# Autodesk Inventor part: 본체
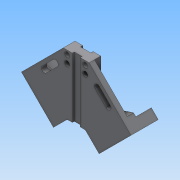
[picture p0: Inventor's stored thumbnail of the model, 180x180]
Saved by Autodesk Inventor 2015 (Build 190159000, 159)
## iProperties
Created: 2019-04
Part Number: 본체
Material: 일반
Document SubType Name: Modeling
Designer: SCD-A01
Density: 1 g/cm^3
Appearance: 기본값
Author: SCD-A01
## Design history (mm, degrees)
sketch "스케치1"
  geometry: L1 (84.853, 0)-(0, 84.853); L2 (0, 84.853)-(-84.853, 0); L3 (-84.853, 0)-(0, -84.853); L4 (0, -84.853)-(84.853, 0); L5 (84.853, 0)-(-84.853, 0); L6 (0, -84.853)-(0, 84.853); L7 (100, 0)-(-100, 0); 4 further points
  constraints: 14 end point, 3 midpoint, 2 coincident, 2 perpendicular, 1 horizontal, 1 point on line
  dimensions: "d2" = 120 distance of L1.start L1.end; "d3" = 120 distance of L1.end L2.end; "d4" = 120 distance of L2.end L3.end; "d5" = 200 distance of L7.start L7.end
extrude "돌출1" new body sketch "스케치1" distance "d6" = 42; taper "d7" = 0 deg
sketch "스케치2"
  geometry: L1 (-84.853, 0)-(0, -84.853) reference; L2 (-20, -64.853)-(20, -64.853); L3 (-20, -64.853)-(0, -84.853); L4 (20, -64.853)-(0, -84.853); 1 further point
  constraints: 6 end point, 1 horizontal, 1 point on line
  dimensions: "d8" = 40 distance of L2.start L2.end; "d9" = 20 distance from line of L1.end L2
extrude "돌출2" cut sketch "스케치2" distance "d10" = 42; taper "d11" = 0 deg
sketch "스케치3"
  geometry: L1 (-20, -64.853)-(20, -64.853) reference; L2 (0, -64.853)-(0, 28.147); L3 (-84.853, 0)-(0, 84.853); L4 (84.853, 0)-(0, 84.853) reference; L5 (-14.005, 28.147)-(14.005, 28.147); L6 (-14.005, 28.147)-(-35.355, 49.497); L7 (14.005, 28.147)-(35.355, 49.497); L8 (-35.355, 49.497)-(0, 84.853); L9 (0, 84.853)-(35.355, 49.497); 1 further point
  constraints: 14 end point, 2 midpoint, 1 collinear, 1 horizontal, 1 parallel, 1 perpendicular, 1 vertical
  dimensions: "d12" = 93 distance of L2.end L2.start; "d22" = 50 distance between parallel lines of L3 L7; "d23" = 50 distance between parallel lines of L4 L6
extrude "돌출3" cut sketch "스케치3" distance "d24" = 42; taper "d25" = 0 deg
sketch "스케치4"
  geometry: L1 (-35.355, 49.497)-(-84.853, 0) reference; L2 (84.853, 0)-(35.355, 49.497) reference; L3 (-24.749, 38.891)-(-74.246, -10.607); L4 (74.246, -10.607)-(24.749, 38.891); L5 (-74.246, -10.607)-(0, -84.853); L6 (0, -84.853)-(74.246, -10.607); L7 (-24.749, 38.891)-(24.749, 38.891); 1 further point
  constraints: 10 end point, 2 parallel, 1 horizontal
  dimensions: "d26" = 15 distance between parallel lines of L1 L3; "d27" = 15 distance between parallel lines of L2 L4; "d28" = 49.49747 distance of L3.start L4.end; "d30" = 74.24621 horizontal distance of L3.end L5.end; "d31" = 105 distance of L5.end L4.start; "d32" = 90 deg angle of L6 L5; "d33" = 148.49242 distance of L4.start L3.end
extrude "돌출4" cut sketch "스케치4" distance "d34" = 24; taper "d35" = 0 deg
sketch "스케치5"
  geometry: L1 (40, 18)-(0, 18) reference; L2 (12, 18)-(12, 14.5); L3 (12, 14.5)-(28, 14.5); L4 (28, 14.5)-(28, 18); L5 (28, 18)-(12, 18); 2 further points
  constraints: 8 end point, 3 perpendicular, 2 midpoint, 1 vertical
  dimensions: "d39" = 16 distance between parallel lines of L4 L2; "d40" = 3.5 distance of L2.start L2.end
extrude "돌출5" cut sketch "스케치5" stored distance "d41" = 24; taper "d42" = 0 deg
sketch "스케치6"
  geometry: L1 (40, 0)-(0, 0) reference; L2 (14, 0)-(14, 3); L3 (14, 3)-(26, 3); L4 (26, 3)-(26, 0); L5 (26, 0)-(14, 0); 2 further points
  constraints: 8 end point, 2 midpoint, 2 perpendicular, 2 vertical
  dimensions: "d43" = 3 distance of L3.end L4.end; "d44" = 12 distance of L2.end L3.end
extrude "돌출6" cut sketch "스케치6" stored distance "d45" = 24; taper "d46" = 0 deg
sketch "스케치7"
  geometry: L1 (-20, -64.853)-(-74.246, -10.607) reference; L2 (-12.649, -58.062)-(-66.895, -3.816); L3 (-35.355, 49.497)-(-84.853, 0) reference; L4 (-21.213, 35.355)-(-70.711, -14.142); L5 (-12.461, 29.965)-(-61.959, -19.532); L6 (-5.438, -51.131)-(-59.684, 3.115); L7 (-70.711, -14.142)-(-49.497, -7.071); L8 (-26.541, 1.743)-(-76.039, -47.754); L9 (-9.571, -15.228)-(-59.068, -64.725); L10 (-20, -64.853)-(-20, -36.569); L11 (-20, -36.569)-(-49.497, -7.071); L12 (-70.711, -14.142)-(-20, -64.853); 1 further point
  constraints: 20 end point, 6 parallel, 3 point on line, 1 perpendicular, 1 vertical
  dimensions: "d47" = 10 distance between parallel lines of L1 L2; "d48" = 20 distance between parallel lines of L3 L4; "d49" = 30 distance between parallel lines of L3 L5; "d50" = 20 distance between parallel lines of L1 L6; "d51" = 40 distance between parallel lines of L3 L8; "d52" = 24 distance between parallel lines of L8 L9; "d54" = 21.2132 horizontal distance of L4.end L7.end
extrude "돌출7" cut sketch "스케치7" distance "d55" = 10; taper "d56" = 0 deg
sketch "스케치8"
  geometry: L1 (-7.071, 21.213)-(-56.569, -28.284); L2 (9.899, 4.243)-(-39.598, -45.255); L3 (-84.853, 0)-(-20, -64.853) reference; L4 (-77.782, 7.071)-(-12.929, -57.782); L5 (-35.355, 49.497)-(-84.853, 0) reference; L6 (-49.497, -21.213)-(-32.527, -38.184); L7 (-52.679, -24.395)-(-35.709, -41.366); L8 (-29.345, -35.002)-(-46.315, -18.031); A1 r 4.5 centre (-49.497, -21.213) between (-46.315, -18.031) and (-52.679, -24.395); A2 r 4.5 centre (-32.527, -38.184) between (-35.709, -41.366) and (-29.345, -35.002); 2 further points
  constraints: 14 end point, 4 point on circle, 4 point on line, 4 tangent, 3 parallel, 2 centre point, 1 midpoint
  dimensions: "d58" = 24 distance between parallel lines of L1 L2; "d59" = 10 distance between parallel lines of L3 L4; "d60" = 40 distance between parallel lines of L1 L5; "d61" = 9 diameter of A2
extrude "돌출8" cut sketch "스케치8" distance "d62" = 10; taper "d63" = 0 deg
sketch "스케치9"
  geometry: L1 (20, -64.853)-(8, -64.853) reference; L2 (0, 0)-(0, -70); L3 (20, -58.853)-(8, -58.853); L4 (14, 0)-(14, -70); C1 r 2.25 at (14, -58.853)
  constraints: 6 end point, 2 parallel, 1 centre point, 1 midpoint, 1 point on line, 1 vertical
  dimensions: "d64" = 70 distance of L2.start L2.end; "d65" = 6 distance between parallel lines of L1 L3; "d66" = 14 distance between parallel lines of L2 L4; "d67" = 4.5 diameter of C1
extrude "돌출9" cut sketch "스케치9" distance "d68" = 8; taper "d69" = 0 deg
sketch "스케치10"
  geometry: C1 r 2.25 at (14, 58.853) reference; C2 r 4 at (14, 58.853); 1 further point
  constraints: 1 centre point, 1 coincident
  dimensions: "d70" = 8 diameter of C2
extrude "돌출10" cut sketch "스케치10" distance "d71" = 10; taper "d72" = 0 deg
sketch "스케치11"
  geometry: L1 (0, 0)-(0, 72.803); C1 r 4 at (14, 58.853) reference; C2 r 4 at (14, 46.853)
  constraints: 2 end point, 1 centre point, 1 vertical
  dimensions: "d73" = 8 diameter of C2; "d74" = 12 distance of C2.centre C1.centre; "d75" = 14 distance from line of C2.centre L1
extrude "돌출11" cut sketch "스케치11" distance "d76" = 10; taper "d77" = 0 deg
sketch "스케치12"
  geometry: C1 r 4 at (14, -46.853) reference; C2 r 2.25 at (14, -46.853); 1 further point
  constraints: 1 centre point, 1 coincident
  dimensions: "d78" = 4.5 diameter of C2
extrude "돌출12" cut sketch "스케치12" distance "d79" = 10; taper "d80" = 0 deg
fillet "모깎기1" dims "d81" = 5
sketch "스케치13"
  geometry: L1 (-24.749, 38.891)-(-35.355, 49.497) reference; L2 (-35.355, 49.497)-(-84.853, 0) reference; 2 further points
  constraints: 1 other
  dimensions: "d84" = 7.5 distance from line of L2 point (-54.801, 19.445); "d85" = 35 distance from line of L1 point (-54.801, 19.445)
feature "엠보싱1" sketch "스케치13" dims "d2" = 120, "d3" = 120, "d4" = 120, "d5" = 200, "d86" = 0.5, "d87" = 0
node "솔리드1"
mirror "대칭1"
mirror "대칭2"
mirror "대칭3"
